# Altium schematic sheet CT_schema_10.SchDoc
size 274 x 160 mm
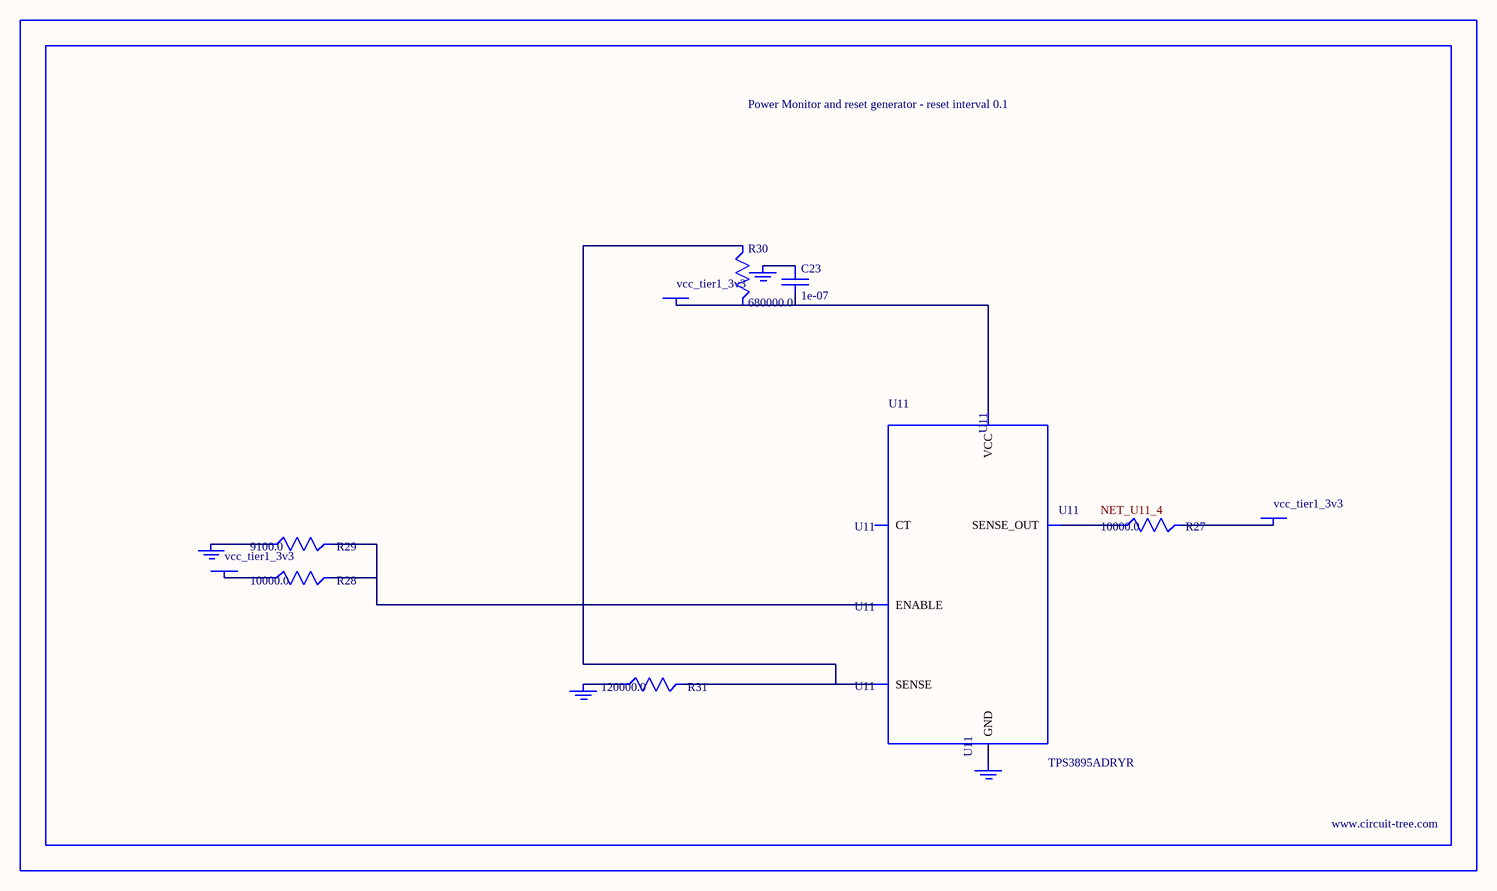
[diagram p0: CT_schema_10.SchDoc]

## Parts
BORDER9  (no value)
C23  1e-07  [C0402]
GND_INSTANCE_9_0  (no value)
GND_INSTANCE_9_1  (no value)
GND_INSTANCE_9_2  (no value)
GND_INSTANCE_9_3  (no value)
POWER_INSTANCE_9_0  vcc_tier1_3v3
POWER_INSTANCE_9_1  vcc_tier1_3v3
POWER_INSTANCE_9_2  vcc_tier1_3v3
R27  10000.0  [R0603]
R28  10000.0  [R0603]
R29  9100.0  [R0603]
R30  680000.0  [R0603]
R31  120000.0  [R0603]
U11  TPS3895ADRYR  [SON-6]

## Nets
NetC23_1: C23.1 GND_INSTANCE_9_2.0(GND)
NetC23_2: C23.2 POWER_INSTANCE_9_2.0(PWR) R30.2 U11.6(VCC)
NetGND_INSTANCE_9_0_0: GND_INSTANCE_9_0.0(GND) R29.1
NetGND_INSTANCE_9_1_0: GND_INSTANCE_9_1.0(GND) R31.1
NetGND_INSTANCE_9_3_0: GND_INSTANCE_9_3.0(GND) U11.2(GND)
NetPOWER_INSTANCE_9_0_0: POWER_INSTANCE_9_0.0(PWR) R28.1
NetPOWER_INSTANCE_9_1_0: POWER_INSTANCE_9_1.0(PWR) R27.2
NetR27_1: R27.1 U11.4(SENSE_OUT)
NetR28_2: R28.2 R29.2 U11.1(ENABLE)
NetR30_1: R30.1 R31.2 U11.3(SENSE)

Not connected (* = marked no-connect by the designer): U11 5(CT)

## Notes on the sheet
- Labels drawn without touching a wire or pin: NET_U11_4

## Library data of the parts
BORDER9 = BORDER_PAGE9
C23 = C0402C104K3RACTU
GND_INSTANCE_9_0-GND_INSTANCE_9_3 = GND
POWER_INSTANCE_9_0-POWER_INSTANCE_9_2 = PWR
R27 R28 = RC0603JR-0710KL
R29 = RC0603JR-079K1L
R30 = RC0603JR-07680KL
R31 = RC0603JR-07120KL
